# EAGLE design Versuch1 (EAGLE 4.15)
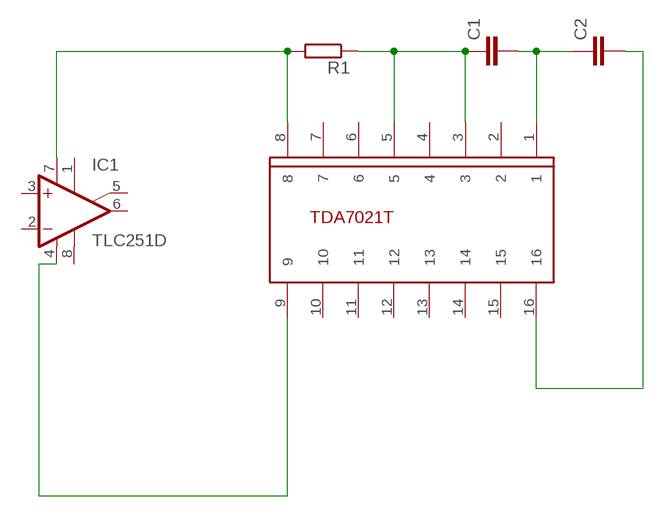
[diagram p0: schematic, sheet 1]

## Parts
C1  C-EUC0805  [C0805]
C2  C-EUC0805  [C0805]
IC1  TLC251D  [SO08]
R1  R-EU_0207/10  [0207/10]
U$1  TDA7021T  [SO-16]

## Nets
N$1: IC1.7(V+) R1.2 U$1.8
N$2: C1.1 R1.1 U$1.3 U$1.5
N$3: C2.2 U$1.16
N$4: C1.2 C2.1 U$1.1
N$5: IC1.4(V-) U$1.9
Unconnected: IC1.1(ON1) IC1.2(-IN) IC1.3(+IN) IC1.5(ON2) IC1.6(OUT) IC1.8(OPT) U$1.2 U$1.6 U$1.7 U$1.10 U$1.11 U$1.12 U$1.13 U$1.14 U$1.15

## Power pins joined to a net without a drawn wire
4: U$1.4

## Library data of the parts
C1 C2 = rcl:C-EU: CAPACITOR, European symbol
IC1 = linear:TLC251: OP AMP
R1 = rcl:R-EU_: RESISTOR, European symbol
U$1 = tda:TDA7021T

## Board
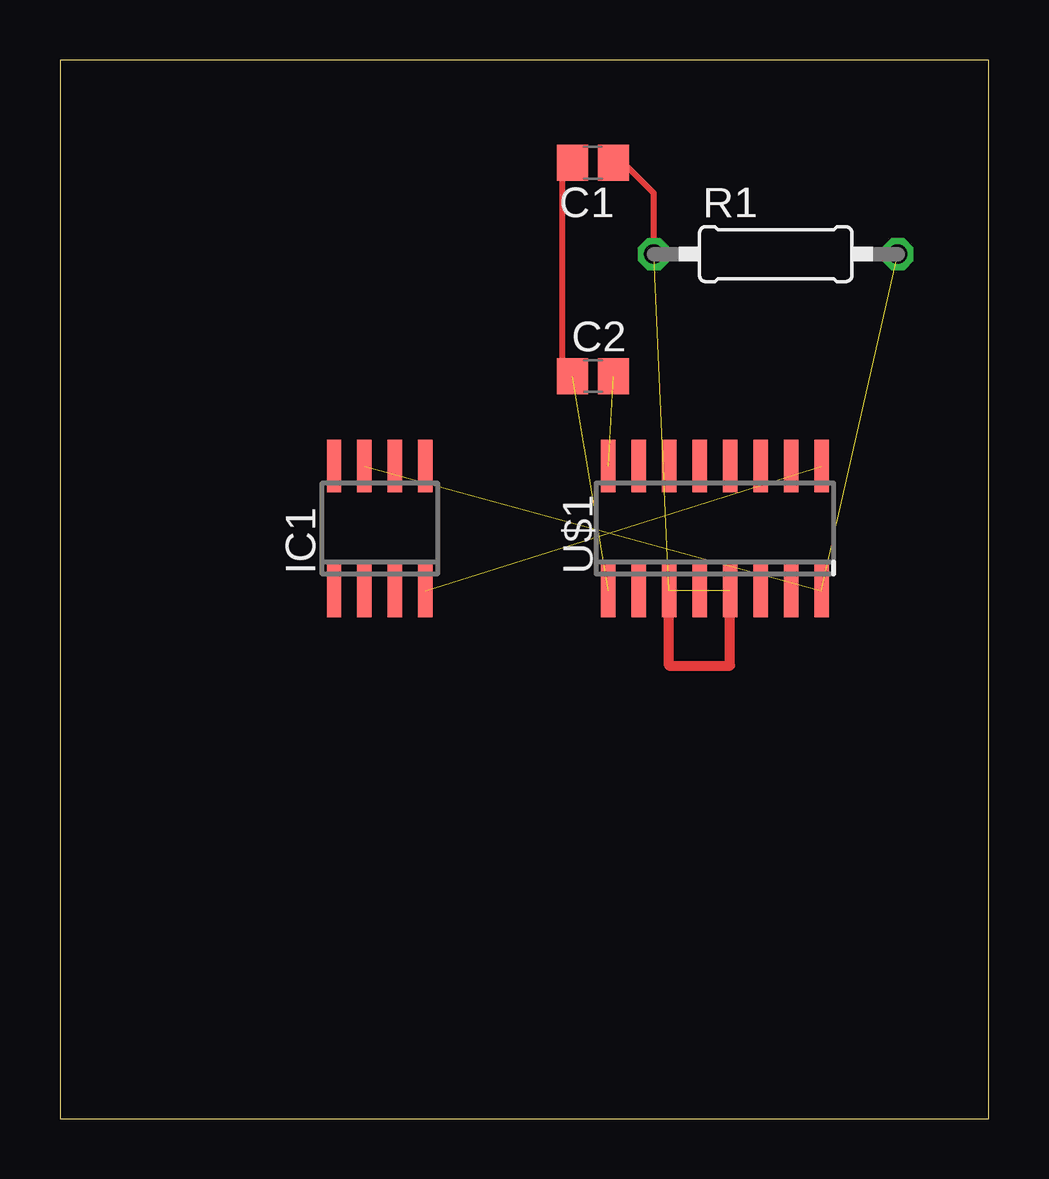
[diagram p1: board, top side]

Size 38.72 x 44.12 mm. Coordinates in mm from the lower left corner, seen from the top.
Outline: 0,0 38.72,0 38.72,44.12 0,44.12 0,0
Copper layers (1*16): Top 0.035mm / dielectric 1.5mm / Bottom 0.035mm
Design rules "default": minimum track width 10mil, minimum drill 24mil, track to track 8mil, track to pad 8mil, pad to pad 8mil, via to via 8mil, smd to smd 8mil, copper to edge 40mil, drill to drill 8mil, minimum pad ring 10mil, minimum via ring 8mil, stop-mask expansion 4mil, vias tented up to drill 0mil, thermal gap 10mil

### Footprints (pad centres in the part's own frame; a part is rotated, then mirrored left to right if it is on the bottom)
C0805 = smd 1.3 x 1.5: 1 -0.85,0; 2 0.85,0
SO08 = smd 0.6 x 2.2: 1 -1.905,-2.6; 2 -0.635,-2.6; 3 0.635,-2.6; 4 1.905,-2.6; 5 1.905,2.6; 6 0.635,2.6; 7 -0.635,2.6; 8 -1.905,2.6
0207/10 = drill 0.813 octagon: 1 -5.08,0; 2 5.08,0
SO-16 = smd 0.6 x 2.2: 1 -4.445,-2.6; 2 -3.175,-2.6; 3 -1.905,-2.6; 4 -0.635,-2.6; 5 0.635,-2.6; 6 1.905,-2.6; 7 3.175,-2.6; 8 4.445,-2.6; 9 4.445,2.6; 10 3.175,2.6; 11 1.905,2.6; 12 0.635,2.6; 13 -0.635,2.6; 14 -1.905,2.6; 15 -3.175,2.6; 16 -4.445,2.6

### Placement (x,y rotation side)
C1  22.22,39.84 180 top
C2  22.22,30.95 0 top
IC1  13.33,24.6 0 top
R1  29.84,36.03 0 top
U$1  27.3,24.6 0 top

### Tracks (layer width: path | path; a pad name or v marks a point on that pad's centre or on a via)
N$1  (2 unrouted)
N$2  (2 unrouted)
  Top 0.254: R1.1 24.76,38.57 23.49,39.84 C1.1
N$3  (1 unrouted)
N$4  (1 unrouted)
  Top 0.254: C2.1 20.95,30.95 20.95,39.84 C1.2
N$5  (1 unrouted)
N$6
  Top 0.406: 25.39,22.06 25.39,18.88 27.93,18.88 27.93,22.06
